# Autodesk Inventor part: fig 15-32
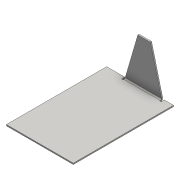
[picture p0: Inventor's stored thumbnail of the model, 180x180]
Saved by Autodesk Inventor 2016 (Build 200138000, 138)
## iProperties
Created: 2015-07
Part Number: fig 15-32
Material: Generic
Document SubType Name: Sheet Metal
Designer: Sandeep
Density: 1 g/cm^3
Sheet Metal Rule: Default_mm
Appearance: Default
Author: Sandeep
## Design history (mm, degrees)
node "Face1"
  sketch "Sketch1"
    geometry: L1 (-13.665, -20.614)-(13.431, -20.614); L2 (13.431, -20.614)-(13.431, 19.99); L3 (13.431, 19.99)-(-13.665, 19.99); L4 (-13.665, 19.99)-(-13.665, -20.614); 1 further point
    constraints: 8 end point, 2 parallel, 1 horizontal, 1 perpendicular
node "Face4"
  sketch "Sketch4"
    geometry: L1 (0, -0.5)-(27.096, -0.5); L2 (27.096, 0)-(0, 0); L3 (0, 0)-(27.096, 0); L4 (7.897, -0.5)-(13.115, -18.469); L5 (13.115, -18.469)-(18.194, -18.469); L6 (18.194, -18.469)-(22.807, -0.5); L7 (7.897, -0.5)-(22.807, -0.5); 1 further point
    constraints: 14 end point, 2 point on line, 1 collinear
body "Solid1"
face "Plate1" dims "Thickness" = 0.5
face "Plate4" dims "d11" = 0.5 (= BendRadius), "d12" = 0.5 (= BendReliefWidth), "d14" = 1 (= MinimumRemnant), "Thickness" = 0.5
bend "Bend3" dims "d11" = 0.5 (= BendRadius), "d12" = 0.5 (= BendReliefWidth), "d13" = 0.25 (= BendReliefDepth), "d14" = 1 (= MinimumRemnant), "d15" = 0.5 (= BendRadius), "SeamGap" = 0.01, "Thickness" = 0.5
other parameters: "BendRadius" = 0.5 (= Thickness), "BendReliefWidth" = 0.5 (= Thickness), "BendReliefDepth" = 0.25 (= 0.5 x Thickness), "CornerReliefSize" = 2 (= 4 x Thickness), "MinimumRemnant" = 1 (= 2 x Thickness), "TransitionRadius" = 0.5 (= BendRadius), "JacobiRadiusSize" = 0.5 (= BendRadius), "GapSize" = 0.5 (= Thickness), "d0" = 0.5 (= BendRadius)
